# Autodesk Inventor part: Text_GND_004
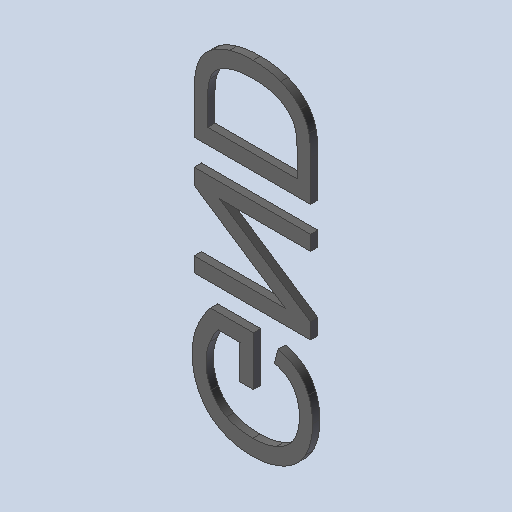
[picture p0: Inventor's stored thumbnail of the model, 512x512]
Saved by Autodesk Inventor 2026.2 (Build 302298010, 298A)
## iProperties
Created: 2026-10
Part Number: Text_GND_004
Material: Générique
Document SubType Name: Modeling
Designer: mel
Density: 1 g/cm^3
Appearance: Par défaut
Author: mel
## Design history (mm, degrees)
feature "Base1"
feature "Base2"
feature "Base3"
node "Solide1"
node "Solide2"
node "Solide3"
